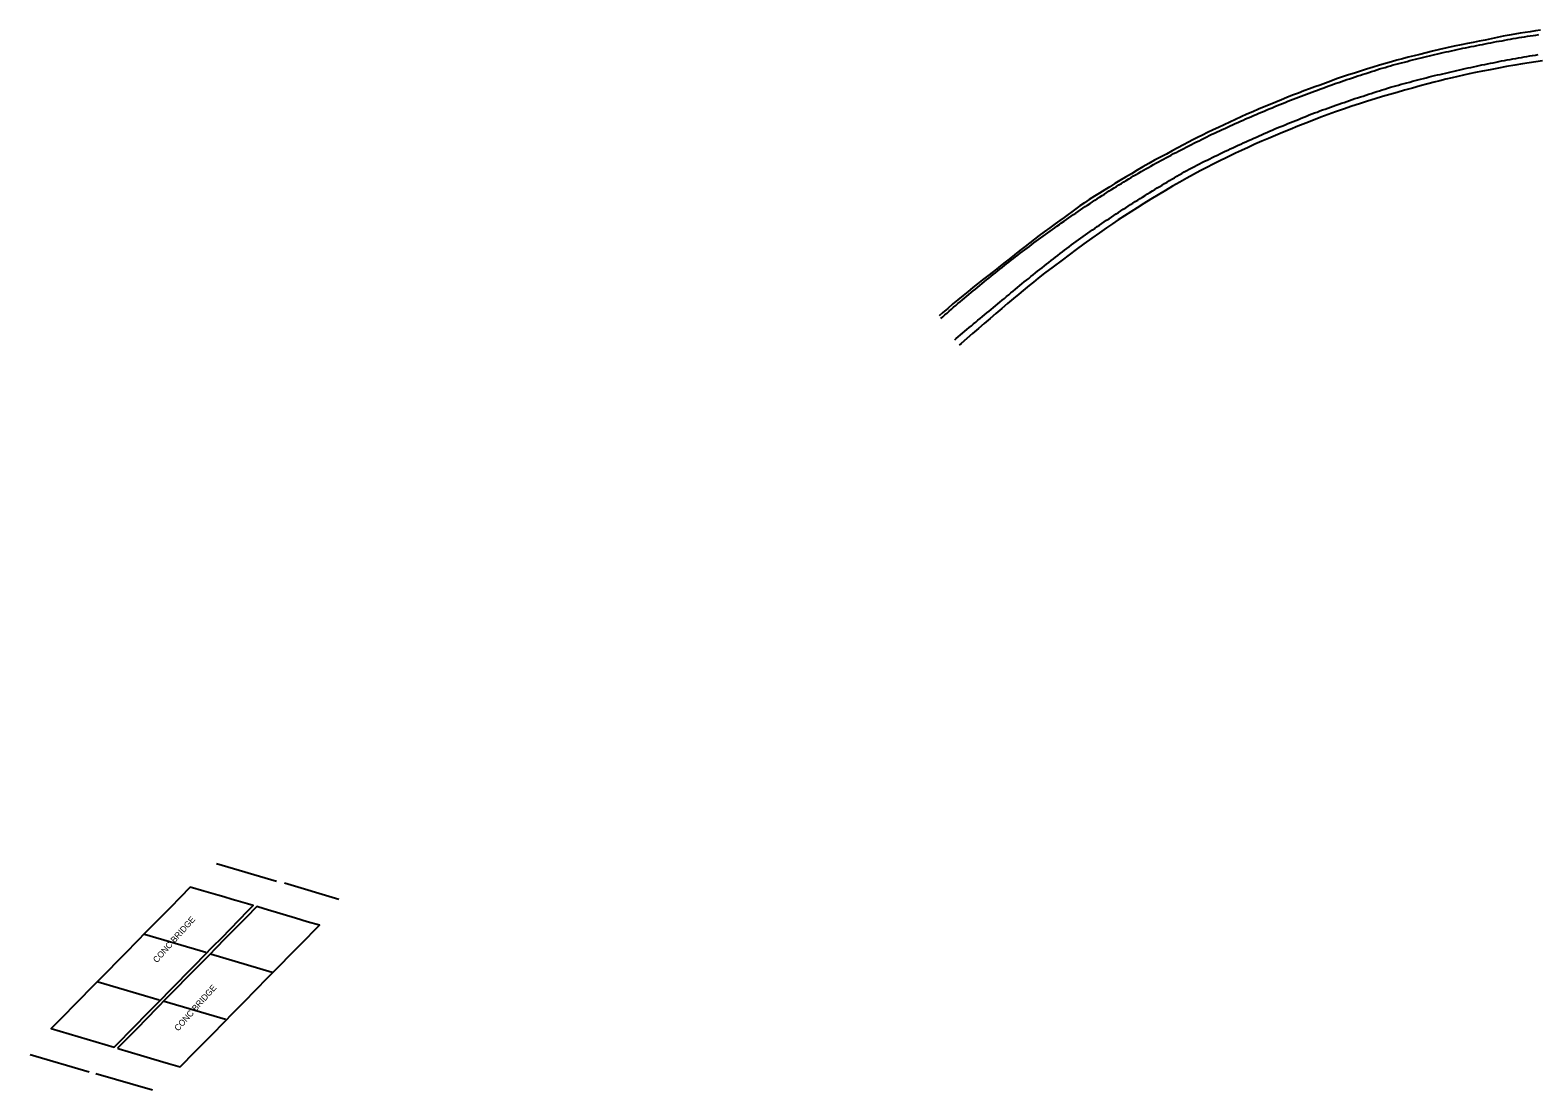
# Model space of a CAD drawing. Extents: x 1961683 to 1977751, y 798292 to 805767.
# Drawn here: x 1961683 to 1963001, y 798292 to 799218 of the extents above; entities that cross this region are included whole.
import ezdxf

# ---------------------------------------------------------------- set-up
doc = ezdxf.new("R2010")
doc.units = 0
for name, color, linetype in [('RD_EX_Bridge', 7, 'Continuous'), ('RD_EX_Bridge_Seam', 7, 'Continuous'), ('RD_EX_Conc', 7, 'Continuous'), ('RD_EX_Road', 7, 'Continuous'), ('RD_EX_Road_Paint', 7, 'Continuous'), ('RD_TX_RoadID', 7, 'Continuous')]:
    doc.layers.add(name, color=color, linetype=linetype)

msp = doc.modelspace()

# ---------------------------------------------------------------- linework, layer by layer
at = {"layer": 'RD_EX_Bridge'}
msp.add_lwpolyline([(1961756.2, 798329.4), (1961762.5, 798335.7), (1961768.7, 798342.2), (1961775.9, 798349.4), (1961783.1, 798356.7), (1961790.3, 798364.1), (1961797.5, 798371.4), (1961804.7, 798378.8), (1961811.9, 798386.1), (1961819.5, 798393.8), (1961827.2, 798401.7), (1961835, 798409.5), (1961842.6, 798417.3), (1961850.2, 798425.1), (1961857.9, 798432.9), (1961865.6, 798440.7), (1961873.2, 798448.5), (1961877.8, 798453.2), (1961872.8, 798454.6), (1961866.6, 798456.4), (1961862.6, 798457.5), (1961859.5, 798458.5), (1961852, 798460.7), (1961846.7, 798462.2), (1961842.7, 798463.4), (1961834.6, 798465.8), (1961822.7, 798469.2), (1961814, 798460.3), (1961805.4, 798451.6), (1961800, 798446.1), (1961789.8, 798435.7), (1961784, 798429.9), (1961776, 798421.7), (1961766.4, 798412), (1961760.3, 798405.8), (1961749.2, 798394.5), (1961741.7, 798386.9), (1961734.2, 798379.2), (1961727.6, 798372.5), (1961720.2, 798365), (1961713.3, 798358), (1961701.3, 798345.8), (1961756.2, 798329.4), (1961756.2, 798329.4)], dxfattribs=at)
msp.add_lwpolyline([(1961759.1, 798328.5), (1961759.3, 798328.4), (1961760.7, 798328), (1961768.4, 798325.7), (1961782.2, 798321.5), (1961790.8, 798319), (1961803.7, 798315.2), (1961813.9, 798312.2), (1961827.3, 798325.8), (1961834.5, 798333.2), (1961842.1, 798340.8), (1961852.5, 798351.4), (1961860.2, 798359.3), (1961869.6, 798368.9), (1961880.2, 798379.7), (1961890.1, 798389.8), (1961900.4, 798400.3), (1961911, 798411.1), (1961919, 798419.2), (1961935.6, 798436), (1961924.9, 798439.1), (1961914.6, 798442.2), (1961903.8, 798445.4), (1961887.2, 798450.4), (1961880.8, 798452.3), (1961871.7, 798442.9), (1961858, 798429), (1961852.5, 798423.4), (1961846, 798416.8), (1961838.6, 798409.4), (1961829.1, 798399.6), (1961819.5, 798389.9), (1961810.8, 798381.1), (1961802.1, 798372.2), (1961793.5, 798363.4), (1961784.8, 798354.6), (1961776, 798345.6), (1961766.9, 798336.4)], close=True, dxfattribs=at)
at = {"layer": 'RD_EX_Bridge_Seam'}
for p, q in [((1961836.3, 798412.2), (1961782.6, 798427.9)), ((1961840.5, 798410.9), (1961894.2, 798394.9)), ((1961742.1, 798386.6), (1961795.7, 798370.7)), ((1961853.4, 798353.6), (1961799.8, 798369.4))]:
    msp.add_line(p, q, dxfattribs=at)
at = {"layer": 'RD_EX_Conc'}
for p, q in [((1961845.7, 798490), (1961898.1, 798474.6)), ((1961952.7, 798458.6), (1961905.2, 798472.7)), ((1961682.8, 798323.1), (1961734.5, 798308)), ((1961740.1, 798306.4), (1961789.6, 798292.1))]:
    msp.add_line(p, q, dxfattribs=at)
at = {"layer": 'RD_EX_Road'}
for points in [[(1963003, 799218.4), (1962998.5, 799217.7), (1962994, 799217), (1962989.6, 799216.3), (1962985.2, 799215.6), (1962980.6, 799214.8), (1962975.6, 799214), (1962970.3, 799213), (1962965, 799211.9), (1962959.8, 799210.8), (1962954.5, 799209.7), (1962949.3, 799208.7), (1962944.2, 799207.7), (1962939, 799206.7), (1962933.5, 799205.6), (1962927.6, 799204.4), (1962921.2, 799203), (1962914.7, 799201.5), (1962908.6, 799200), (1962902.9, 799198.5), (1962897.6, 799197.2), (1962892.4, 799195.9), (1962887.3, 799194.6), (1962882.3, 799193.2), (1962877.4, 799192), (1962872.6, 799190.7), (1962867.6, 799189.3), (1962862.3, 799187.8), (1962856.6, 799186.1), (1962850.9, 799184.3), (1962845.6, 799182.6), (1962840.4, 799180.9), (1962835.1, 799179.2), (1962829.8, 799177.5), (1962824.6, 799175.7), (1962819.6, 799173.9), (1962814.9, 799172.1), (1962810.3, 799170.4), (1962805.7, 799168.7), (1962801, 799167), (1962796.2, 799165.2), (1962791.4, 799163.4), (1962786.3, 799161.4), (1962781.3, 799159.4), (1962776.5, 799157.5), (1962771.6, 799155.5), (1962766.6, 799153.4), (1962761.5, 799151.3), (1962756.5, 799149.2), (1962751.5, 799147), (1962746.4, 799144.8), (1962741.4, 799142.5), (1962736.3, 799140.2), (1962731.3, 799137.9), (1962726.4, 799135.6), (1962721.5, 799133.4), (1962716.7, 799131.2), (1962712, 799128.9), (1962707.5, 799126.7), (1962703.2, 799124.6), (1962699.2, 799122.5), (1962695.2, 799120.4), (1962690.8, 799118.1), (1962686, 799115.5), (1962681, 799112.9), (1962675.9, 799110.1), (1962670.8, 799107.4), (1962665.7, 799104.6), (1962660.6, 799101.7), (1962655.5, 799098.8), (1962650.5, 799095.9), (1962645.4, 799092.9), (1962640.3, 799089.8), (1962635.4, 799086.9), (1962630.9, 799084.2), (1962626.6, 799081.5), (1962622.1, 799078.8), (1962617.5, 799076), (1962613, 799073.2), (1962608.5, 799070.3), (1962604.3, 799067.5), (1962600.4, 799064.7), (1962596.8, 799062.1), (1962593.4, 799059.6), (1962590, 799057.1), (1962586.5, 799054.7), (1962582.8, 799052), (1962578.8, 799049), (1962574, 799045.6), (1962569.2, 799042), (1962564.8, 799038.8), (1962560.7, 799035.7), (1962556.6, 799032.5), (1962552.4, 799029.2), (1962547.8, 799025.7), (1962543.1, 799022), (1962538.4, 799018.3), (1962533.8, 799014.6), (1962529.3, 799011), (1962524.7, 799007.4), (1962519.9, 799003.7), (1962515.2, 799000), (1962510.9, 798996.7), (1962506.9, 798993.5), (1962502.6, 798990), (1962498.2, 798986.4), (1962493.7, 798982.7), (1962489.2, 798979), (1962484.8, 798975.2), (1962480.6, 798971.6), (1962477.2, 798968.6)], [(1963004.7, 799191.6), (1962998.8, 799190.8), (1962993.1, 799189.9), (1962987.2, 799188.9), (1962980.5, 799187.8), (1962973.3, 799186.5), (1962966.1, 799185.2), (1962959, 799183.8), (1962952.2, 799182.5), (1962946.1, 799181.3), (1962940.7, 799180.2), (1962935.7, 799179.1), (1962930.7, 799177.9), (1962925.6, 799176.7), (1962920.3, 799175.4), (1962915, 799174.1), (1962909.9, 799172.8), (1962904.4, 799171.4), (1962897.9, 799169.6), (1962891, 799167.6), (1962884.2, 799165.8), (1962877.7, 799164), (1962871.3, 799162.2), (1962864.9, 799160.4), (1962858.3, 799158.4), (1962851.6, 799156.3), (1962844.8, 799154.1), (1962837.9, 799151.8), (1962830.8, 799149.3), (1962823.8, 799146.9), (1962817.3, 799144.5), (1962810.8, 799142.2), (1962804.4, 799139.7), (1962797.8, 799137.1), (1962790.9, 799134.3), (1962784, 799131.5), (1962777.4, 799128.8), (1962771.2, 799126.3), (1962765.2, 799123.8), (1962759.4, 799121.3), (1962753.3, 799118.6), (1962747.3, 799115.9), (1962741.6, 799113.3), (1962736.4, 799110.9), (1962732.3, 799108.9), (1962728.1, 799106.9), (1962722.7, 799104.2), (1962716.9, 799101.2), (1962711.2, 799098.3), (1962705.5, 799095.3), (1962699.7, 799092.3), (1962693.8, 799089.1), (1962687.6, 799085.6), (1962681.4, 799081.9), (1962675.1, 799078.3), (1962668.8, 799074.5), (1962662.4, 799070.6), (1962656.2, 799066.7), (1962650.4, 799063.1), (1962644.8, 799059.6), (1962639.3, 799056), (1962633.9, 799052.5), (1962628.9, 799049.2), (1962623.7, 799045.6), (1962617.6, 799041.3), (1962610.9, 799036.5), (1962603.9, 799031.5), (1962597.2, 799026.5), (1962591.1, 799022.1), (1962584.8, 799017.4), (1962577, 799011.6), (1962569.5, 799005.9), (1962564, 799001.6), (1962559.7, 798998.2), (1962556, 798995.2), (1962550.9, 798990.9), (1962547, 798987.6), (1962542.3, 798983.7), (1962537.2, 798979.3), (1962532.1, 798975), (1962527, 798970.6), (1962521.8, 798966.3), (1962516.7, 798961.9), (1962511.6, 798957.6), (1962506.6, 798953.2), (1962501.5, 798948.8), (1962496.5, 798944.5), (1962494.7, 798943)]]:
    msp.add_lwpolyline(points, dxfattribs=at)
at = {"layer": 'RD_EX_Road_Paint'}
for points in [[(1962478.9, 798966.3), (1962480.6, 798967.8), (1962482.4, 798969.5), (1962484.3, 798971.1), (1962486.2, 798972.8), (1962488.1, 798974.4), (1962490, 798976.1), (1962491.9, 798977.7), (1962493.8, 798979.3), (1962495.7, 798980.9), (1962497.6, 798982.5), (1962499.5, 798984.1), (1962501.4, 798985.8), (1962503.3, 798987.4), (1962505.2, 798989), (1962507.2, 798990.6), (1962509.1, 798992.1), (1962511, 798993.7), (1962513, 798995.3), (1962514.9, 798996.9), (1962516.8, 798998.5), (1962518.8, 799000.1), (1962520.7, 799001.6), (1962522.7, 799003.2), (1962524.6, 799004.7), (1962526.6, 799006.3), (1962528.5, 799007.9), (1962530.5, 799009.4), (1962532.4, 799011), (1962534.4, 799012.6), (1962536.3, 799014.1), (1962538.3, 799015.7), (1962540.3, 799017.2), (1962542.2, 799018.8), (1962544.2, 799020.3), (1962546.2, 799021.8), (1962548.2, 799023.3), (1962550.2, 799024.8), (1962552.2, 799026.3), (1962554.2, 799027.8), (1962556.2, 799029.3), (1962558.2, 799030.9), (1962560.2, 799032.4), (1962562.2, 799033.8), (1962564.2, 799035.3), (1962566.2, 799036.8), (1962568.2, 799038.3), (1962570.2, 799039.8), (1962572.3, 799041.2), (1962574.3, 799042.7), (1962576.3, 799044.2), (1962578.3, 799045.7), (1962580.3, 799047.1), (1962582.4, 799048.5), (1962584.4, 799050), (1962586.5, 799051.4), (1962588.5, 799052.8), (1962590.6, 799054.3), (1962592.6, 799055.7), (1962594.7, 799057.1), (1962596.8, 799058.5), (1962598.8, 799059.9), (1962600.9, 799061.4), (1962603, 799062.8), (1962605, 799064.1), (1962607.1, 799065.5), (1962609.2, 799066.9), (1962611.3, 799068.3), (1962613.4, 799069.7), (1962615.5, 799071), (1962617.6, 799072.4), (1962619.7, 799073.8), (1962621.8, 799075.1), (1962623.9, 799076.5), (1962626, 799077.8), (1962628.1, 799079.1), (1962630.2, 799080.5), (1962632.3, 799081.8), (1962634.5, 799083.1), (1962636.6, 799084.4), (1962638.7, 799085.7), (1962640.9, 799087), (1962643, 799088.3), (1962645.1, 799089.6), (1962647.3, 799090.9), (1962649.4, 799092.1), (1962651.6, 799093.4), (1962653.8, 799094.7), (1962655.9, 799095.9), (1962658.1, 799097.1), (1962660.3, 799098.4), (1962662.4, 799099.6), (1962664.6, 799100.8), (1962666.8, 799102), (1962669, 799103.2), (1962671.2, 799104.4), (1962673.4, 799105.6), (1962675.6, 799106.8), (1962677.8, 799108), (1962680, 799109.2), (1962682.2, 799110.4), (1962684.4, 799111.5), (1962686.6, 799112.7), (1962688.9, 799113.8), (1962691.1, 799115), (1962693.3, 799116.1), (1962695.5, 799117.3), (1962697.8, 799118.4), (1962700, 799119.5), (1962702.2, 799120.6), (1962704.5, 799121.7), (1962706.7, 799122.8), (1962709, 799124), (1962711.2, 799125.1), (1962713.4, 799126.2), (1962715.7, 799127.3), (1962717.9, 799128.3), (1962720.2, 799129.4), (1962722.5, 799130.5), (1962724.7, 799131.5), (1962727, 799132.5), (1962729.3, 799133.6), (1962731.6, 799134.6), (1962733.8, 799135.7), (1962736.1, 799136.7), (1962738.4, 799137.7), (1962740.7, 799138.7), (1962743, 799139.7), (1962745.2, 799140.8), (1962747.5, 799141.7), (1962749.8, 799142.7), (1962752.1, 799143.7), (1962754.4, 799144.7), (1962756.7, 799145.7), (1962759, 799146.6), (1962761.3, 799147.6), (1962763.6, 799148.6), (1962765.9, 799149.6), (1962768.3, 799150.5), (1962770.6, 799151.5), (1962772.9, 799152.4), (1962775.2, 799153.3), (1962777.5, 799154.3), (1962779.8, 799155.2), (1962782.2, 799156.2), (1962784.5, 799157.1), (1962786.8, 799158), (1962789.1, 799158.9), (1962791.5, 799159.8), (1962793.8, 799160.7), (1962796.1, 799161.6), (1962798.5, 799162.5), (1962800.8, 799163.3), (1962803.2, 799164.2), (1962805.5, 799165.1), (1962807.9, 799165.9), (1962810.2, 799166.7), (1962812.6, 799167.6), (1962814.9, 799168.5), (1962817.2, 799169.4), (1962819.6, 799170.3), (1962821.9, 799171.1), (1962824.3, 799171.9), (1962826.7, 799172.7), (1962829, 799173.5), (1962831.4, 799174.3), (1962833.8, 799175.1), (1962836.1, 799175.9), (1962838.5, 799176.8), (1962840.9, 799177.5), (1962843.2, 799178.3), (1962845.6, 799179.1), (1962848, 799179.9), (1962850.4, 799180.6), (1962852.8, 799181.4), (1962855.1, 799182.2), (1962857.5, 799182.9), (1962859.9, 799183.7), (1962862.3, 799184.5), (1962864.7, 799185.1), (1962867.1, 799185.8), (1962869.5, 799186.5), (1962871.9, 799187.2), (1962874.3, 799187.9), (1962876.7, 799188.5), (1962879.1, 799189.2), (1962881.5, 799189.9), (1962884, 799190.5), (1962886.4, 799191.1), (1962888.8, 799191.8), (1962891.2, 799192.4), (1962893.6, 799193), (1962896.1, 799193.6), (1962898.5, 799194.2), (1962900.9, 799194.8), (1962903.3, 799195.4), (1962905.8, 799195.9), (1962908.2, 799196.5), (1962910.6, 799197.1), (1962913.1, 799197.7), (1962915.5, 799198.2), (1962918, 799198.7), (1962920.4, 799199.3), (1962922.8, 799199.8), (1962925.3, 799200.3), (1962927.7, 799200.9), (1962930.2, 799201.5), (1962932.6, 799202), (1962935.1, 799202.5), (1962937.5, 799203), (1962940, 799203.5), (1962942.4, 799204), (1962944.9, 799204.5), (1962947.3, 799205), (1962949.8, 799205.4), (1962952.2, 799205.9), (1962954.7, 799206.4), (1962957.1, 799206.9), (1962959.6, 799207.4), (1962962, 799207.8), (1962964.5, 799208.3), (1962966.9, 799208.7), (1962969.4, 799209.1), (1962971.9, 799209.6), (1962974.3, 799210.1), (1962976.8, 799210.5), (1962979.2, 799211), (1962981.7, 799211.4), (1962984.2, 799211.8), (1962986.6, 799212.2), (1962989.1, 799212.6), (1962991.6, 799213), (1962994, 799213.3), (1962996.5, 799213.7), (1962999, 799214.1), (1963001.5, 799214.5)], [(1962491, 798947.8), (1962492.1, 798948.7), (1962494, 798950.3), (1962495.9, 798952), (1962497.8, 798953.6), (1962499.7, 798955.2), (1962501.6, 798956.8), (1962503.5, 798958.4), (1962505.5, 798960), (1962507.4, 798961.6), (1962509.3, 798963.2), (1962511.2, 798964.8), (1962513.2, 798966.4), (1962515.1, 798968), (1962517, 798969.6), (1962518.9, 798971.2), (1962520.9, 798972.7), (1962522.8, 798974.3), (1962524.7, 798975.9), (1962526.6, 798977.5), (1962528.6, 798979.1), (1962530.5, 798980.7), (1962532.4, 798982.3), (1962534.3, 798983.9), (1962536.3, 798985.5), (1962538.2, 798987.1), (1962540.1, 798988.7), (1962542, 798990.3), (1962544, 798991.9), (1962545.9, 798993.5), (1962547.8, 798995.1), (1962549.7, 798996.7), (1962551.7, 798998.3), (1962553.6, 798999.9), (1962555.6, 799001.4), (1962557.5, 799003), (1962559.5, 799004.5), (1962561.4, 799006.1), (1962563.4, 799007.6), (1962565.4, 799009.2), (1962567.3, 799010.7), (1962569.3, 799012.3), (1962571.2, 799013.8), (1962573.2, 799015.4), (1962575.2, 799016.9), (1962577.2, 799018.4), (1962579.1, 799020), (1962581.1, 799021.5), (1962583.1, 799023), (1962585.1, 799024.6), (1962587, 799026.1), (1962589, 799027.6), (1962591, 799029.1), (1962593, 799030.6), (1962595, 799032.1), (1962597.1, 799033.6), (1962599.1, 799035), (1962601.1, 799036.5), (1962603.1, 799038), (1962605.2, 799039.4), (1962607.2, 799040.8), (1962609.3, 799042.3), (1962611.3, 799043.7), (1962613.4, 799045.1), (1962615.4, 799046.6), (1962617.5, 799048), (1962619.6, 799049.4), (1962621.6, 799050.8), (1962623.7, 799052.2), (1962625.8, 799053.5), (1962627.9, 799054.9), (1962629.9, 799056.3), (1962632, 799057.7), (1962634.1, 799059.1), (1962636.2, 799060.4), (1962638.3, 799061.8), (1962640.4, 799063.1), (1962642.5, 799064.5), (1962644.6, 799065.9), (1962646.7, 799067.2), (1962648.8, 799068.5), (1962651, 799069.9), (1962653.1, 799071.2), (1962655.2, 799072.5), (1962657.3, 799073.9), (1962659.4, 799075.2), (1962661.6, 799076.5), (1962663.7, 799077.8), (1962665.8, 799079.1), (1962668, 799080.4), (1962670.1, 799081.7), (1962672.3, 799083), (1962674.4, 799084.3), (1962676.5, 799085.5), (1962678.7, 799086.8), (1962680.8, 799088.1), (1962683, 799089.4), (1962685.1, 799090.7), (1962687.2, 799092), (1962689.4, 799093.2), (1962691.6, 799094.4), (1962693.8, 799095.6), (1962696, 799096.8), (1962698.2, 799098), (1962700.4, 799099.2), (1962702.6, 799100.4), (1962704.8, 799101.6), (1962707, 799102.7), (1962709.3, 799103.8), (1962711.5, 799104.8), (1962713.8, 799105.9), (1962716, 799107), (1962718.3, 799108.1), (1962720.5, 799109.2), (1962722.8, 799110.3), (1962725, 799111.4), (1962727.3, 799112.5), (1962729.6, 799113.5), (1962731.8, 799114.6), (1962734.1, 799115.6), (1962736.4, 799116.7), (1962738.7, 799117.7), (1962740.9, 799118.7), (1962743.2, 799119.8), (1962745.5, 799120.8), (1962747.7, 799121.9), (1962750, 799122.9), (1962752.3, 799123.9), (1962754.6, 799124.9), (1962756.9, 799125.9), (1962759.2, 799126.9), (1962761.5, 799128), (1962763.7, 799129), (1962766, 799130), (1962768.3, 799131), (1962770.6, 799132), (1962772.9, 799132.9), (1962775.2, 799133.9), (1962777.6, 799134.8), (1962779.9, 799135.7), (1962782.2, 799136.7), (1962784.5, 799137.6), (1962786.8, 799138.6), (1962789.1, 799139.5), (1962791.5, 799140.4), (1962793.8, 799141.4), (1962796.1, 799142.4), (1962798.4, 799143.3), (1962800.7, 799144.2), (1962803, 799145.1), (1962805.4, 799146), (1962807.7, 799146.8), (1962810.1, 799147.7), (1962812.4, 799148.6), (1962814.8, 799149.4), (1962817.1, 799150.2), (1962819.5, 799151.1), (1962821.8, 799151.9), (1962824.2, 799152.8), (1962826.6, 799153.6), (1962828.9, 799154.4), (1962831.3, 799155.2), (1962833.7, 799156), (1962836, 799156.8), (1962838.4, 799157.7), (1962840.8, 799158.5), (1962843.1, 799159.2), (1962845.5, 799160), (1962847.9, 799160.8), (1962850.3, 799161.6), (1962852.6, 799162.4), (1962855, 799163.1), (1962857.4, 799163.9), (1962859.8, 799164.7), (1962862.1, 799165.4), (1962864.5, 799166.2), (1962866.9, 799166.9), (1962869.3, 799167.6), (1962871.7, 799168.4), (1962874.1, 799169.1), (1962876.5, 799169.8), (1962878.9, 799170.4), (1962881.3, 799171.1), (1962883.7, 799171.7), (1962886.2, 799172.4), (1962888.6, 799173), (1962891, 799173.7), (1962893.4, 799174.3), (1962895.8, 799174.9), (1962898.2, 799175.6), (1962900.7, 799176.2), (1962903.1, 799176.8), (1962905.5, 799177.5), (1962907.9, 799178.1), (1962910.4, 799178.6), (1962912.8, 799179.2), (1962915.2, 799179.7), (1962917.7, 799180.3), (1962920.1, 799180.8), (1962922.5, 799181.4), (1962925, 799181.9), (1962927.4, 799182.5), (1962929.9, 799183.1), (1962932.3, 799183.6), (1962934.7, 799184.2), (1962937.2, 799184.7), (1962939.6, 799185.3), (1962942, 799185.8), (1962944.5, 799186.3), (1962946.9, 799186.9), (1962949.4, 799187.4), (1962951.8, 799187.9), (1962954.3, 799188.4), (1962956.7, 799188.9), (1962959.2, 799189.4), (1962961.6, 799189.9), (1962964.1, 799190.4), (1962966.5, 799190.9), (1962969, 799191.4), (1962971.4, 799191.9), (1962973.9, 799192.3), (1962976.3, 799192.8), (1962978.8, 799193.2), (1962981.3, 799193.6), (1962983.7, 799194.1), (1962986.2, 799194.5), (1962988.7, 799194.9), (1962991.1, 799195.3), (1962993.6, 799195.8), (1962996, 799196.2), (1962998.5, 799196.6), (1963001, 799197)]]:
    msp.add_lwpolyline(points, dxfattribs=at)

# ---------------------------------------------------------------- texts
at = {"layer": 'RD_TX_RoadID'}
for p in [(1961793.6, 798402.7), (1961812.2, 798343)]:
    msp.add_text('CONC BRIDGE', height=5.4, rotation=48.3139, dxfattribs=at).set_placement(p)

doc.saveas('drawing.dxf')
